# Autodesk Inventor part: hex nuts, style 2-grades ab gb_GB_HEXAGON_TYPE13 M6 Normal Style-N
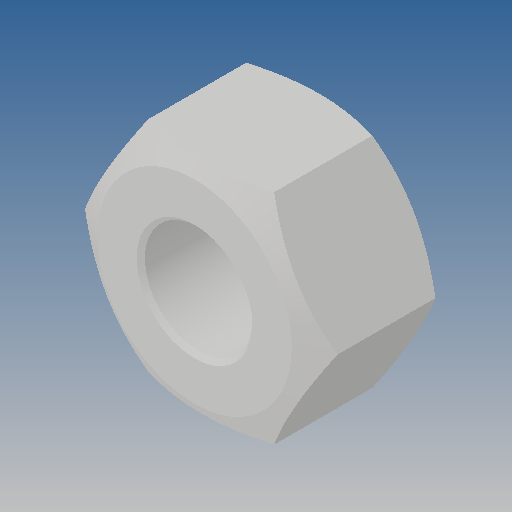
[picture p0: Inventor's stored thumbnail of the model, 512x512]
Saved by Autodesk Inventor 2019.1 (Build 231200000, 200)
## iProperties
Created: 2017-10
Part Number: hex nuts, style 2-grades ab gb_GB_HEXAGON_TYPE13 M6 Normal Style-N
Material: Ogólny
Document SubType Name: Modeling
Designer: CADENGINEERING4
Density: 1 g/cm^3
Appearance: Domyślna
Author: CADENGINEERING4
Revision Number: ÈÎºÎ
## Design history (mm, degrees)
feature "EndChamfer2"
node "Bryła1"
